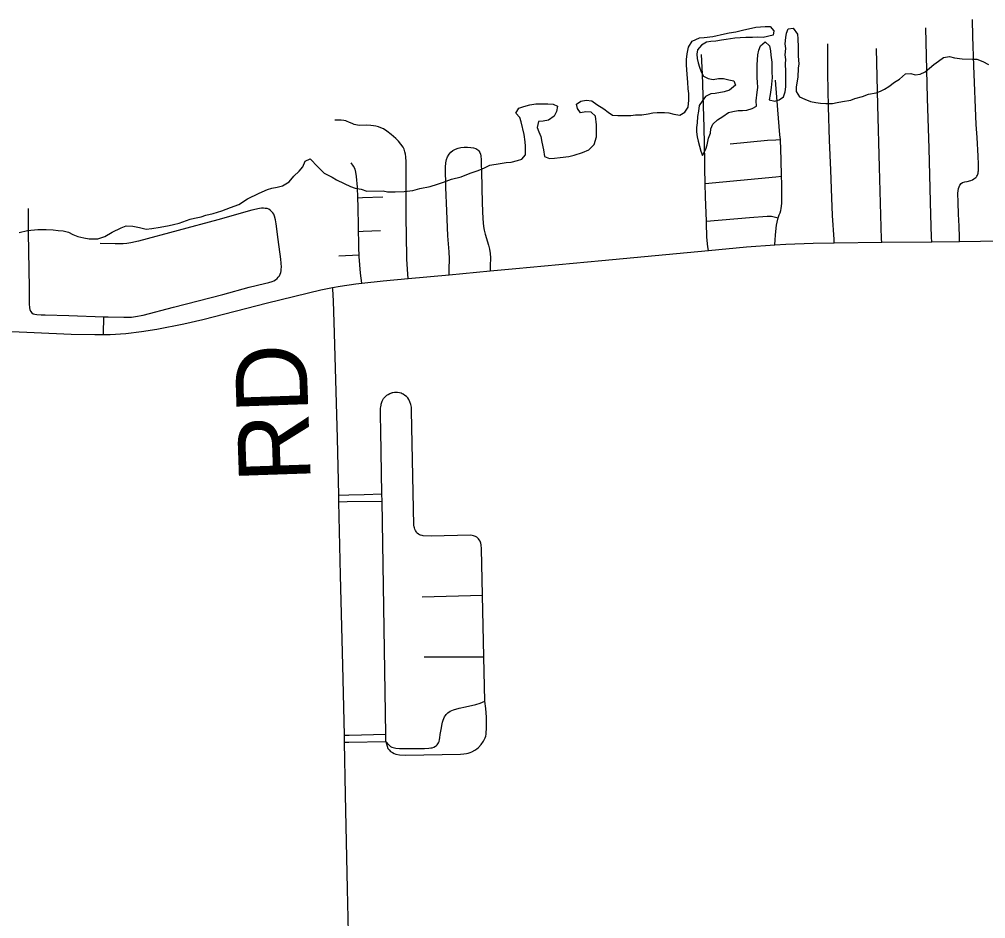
# Model space of a CAD drawing. Extents: x -12 to 34, y 0 to 22.
# Drawn here: x 3.492 to 4.257, y 17.22 to 17.932 of the extents above; entities that cross this region are included whole.
import ezdxf

# ---------------------------------------------------------------- set-up
doc = ezdxf.new("R2010")
doc.units = 0
for name, color, linetype in [('GM_X_Airport_Location_Class_3', 7, 'Continuous'), ('GM_X_County_Road', 7, 'Continuous'), ('GM_X_Major_Lake', 7, 'Continuous'), ('GM_X_Major_River', 7, 'Continuous'), ('GM_X_Minor_Lake', 7, 'Continuous'), ('GM_X_Township', 7, 'Continuous')]:
    doc.layers.add(name, color=color, linetype=linetype)

msp = doc.modelspace()

# ---------------------------------------------------------------- linework, layer by layer
at = {"layer": 'GM_X_Airport_Location_Class_3'}
msp.add_line((3.75011, 17.31777), (3.74933, 17.35937), dxfattribs=at)
for points in [[(3.74486, 17.54981), (3.74473, 17.55506), (3.74366, 17.60023), (3.74151, 17.68333), (3.74072, 17.7089), (3.74006, 17.71833), (3.73991, 17.71962)], [(3.74933, 17.35937), (3.74929, 17.36123), (3.74921, 17.3649), (3.74796, 17.42021), (3.74625, 17.49159), (3.74486, 17.54981)], [(3.75824, 16.94133), (3.75755, 16.97035), (3.75572, 17.05725), (3.75387, 17.15023), (3.75274, 17.19673), (3.75166, 17.24328), (3.75011, 17.31777)]]:
    msp.add_lwpolyline(points, dxfattribs=at)
at = {"layer": 'GM_X_Major_Lake'}
msp.add_lwpolyline([(3.47989, 17.68498), (3.5327, 17.68269), (3.55133, 17.68225), (3.55821, 17.68234), (3.56373, 17.68242), (3.57609, 17.68321), (3.5884, 17.68461), (3.60066, 17.68651), (3.62198, 17.69074), (3.63713, 17.69417), (3.68831, 17.70743), (3.73061, 17.71765), (3.73991, 17.71962), (3.74591, 17.72066), (3.75825, 17.7225), (3.76301, 17.72301), (3.77993, 17.72481), (3.79965, 17.72665), (3.8323, 17.72971), (3.86468, 17.73274), (3.88522, 17.73466), (3.95336, 17.74086), (4.03765, 17.74884), (4.06794, 17.75171), (4.09024, 17.75328), (4.09899, 17.7539), (4.12078, 17.7547), (4.13745, 17.7549), (4.17506, 17.75534), (4.21469, 17.7558), (4.23681, 17.75606), (4.27009, 17.75644)], dxfattribs=at)
at = {"layer": 'GM_X_Major_River'}
for p, q in [((3.74491, 17.74475), (3.76095, 17.74546)), ((3.77909, 17.55039), (3.77899, 17.55604)), ((3.7821, 17.36564), (3.77909, 17.55039)), ((3.81087, 17.47445), (3.85869, 17.47573)), ((3.85967, 17.42691), (3.85869, 17.47573)), ((3.81247, 17.4269), (3.85967, 17.42691)), ((3.86054, 17.39192), (3.85967, 17.42691)), ((3.7822, 17.35994), (3.7821, 17.36564))]:
    msp.add_line(p, q, dxfattribs=at)
for points in [[(4.23681, 17.75606), (4.23673, 17.75937), (4.23652, 17.76807), (4.2359, 17.77761), (4.23563, 17.78685), (4.23548, 17.79438), (4.23563, 17.79623), (4.23598, 17.79803), (4.23639, 17.79941), (4.23701, 17.80072), (4.23798, 17.80196), (4.23915, 17.80265), (4.24087, 17.80327), (4.2428, 17.80362), (4.24556, 17.80437), (4.24694, 17.80486), (4.24812, 17.80555), (4.24893, 17.80606), (4.24963, 17.80665), (4.25013, 17.80713), (4.25053, 17.80769), (4.25093, 17.80855), (4.25122, 17.80941), (4.25142, 17.81017), (4.25157, 17.81107), (4.25168, 17.81184), (4.2517, 17.81273), (4.2517, 17.81417), (4.2517, 17.81728), (4.25143, 17.8236), (4.25081, 17.83839), (4.24996, 17.84863), (4.24812, 17.89526), (4.24728, 17.91849), (4.24707, 17.93196)], [(4.21469, 17.7558), (4.21456, 17.75937), (4.21394, 17.77718), (4.21266, 17.82958), (4.21144, 17.86959), (4.20994, 17.92531)], [(4.13745, 17.7549), (4.13728, 17.75749), (4.13603, 17.77656), (4.13557, 17.79055), (4.13479, 17.8124), (4.13375, 17.83623), (4.13291, 17.86275), (4.13229, 17.88906), (4.13229, 17.91247)], [(4.17506, 17.75534), (4.17499, 17.75791), (4.17332, 17.81489), (4.17207, 17.86399), (4.17104, 17.90896)], [(4.03502, 17.80203), (4.03499, 17.81378), (4.03497, 17.81938), (4.03427, 17.84645), (4.03297, 17.88856), (4.03232, 17.9041)], [(4.09478, 17.83687), (4.09438, 17.84036), (4.09278, 17.86028), (4.09084, 17.88381)], [(3.79965, 17.72665), (3.79946, 17.73023), (3.79881, 17.74193), (3.79874, 17.74423), (3.79821, 17.77557), (3.7981, 17.80647), (3.79816, 17.8192), (3.79792, 17.82293), (3.79768, 17.82523), (3.79721, 17.82701), (3.79655, 17.82909), (3.79573, 17.83062), (3.79401, 17.83317), (3.79206, 17.83548), (3.78992, 17.83767), (3.78625, 17.84075), (3.78288, 17.84341), (3.78014, 17.84515), (3.7782, 17.84613), (3.77613, 17.8469), (3.77424, 17.84737), (3.7724, 17.84767), (3.77021, 17.84797), (3.76672, 17.84808), (3.76089, 17.84793), (3.75962, 17.84806), (3.75829, 17.84836), (3.75696, 17.84873), (3.75582, 17.84914), (3.75283, 17.85059), (3.75144, 17.85113), (3.75026, 17.85152), (3.74877, 17.85183), (3.74663, 17.85196), (3.74171, 17.85206)], [(4.05493, 17.83343), (4.08444, 17.83622), (4.09107, 17.83664), (4.09478, 17.83687)], [(4.09571, 17.80774), (4.0953, 17.82077), (4.09478, 17.83687)], [(3.8323, 17.72971), (3.83239, 17.73395), (3.83257, 17.74228), (3.83239, 17.7479), (3.83115, 17.76034), (3.83044, 17.78017), (3.82955, 17.79877), (3.82937, 17.81488), (3.82962, 17.81827), (3.83023, 17.82106), (3.83099, 17.82318), (3.83215, 17.82505), (3.83351, 17.82662), (3.83518, 17.82799), (3.83734, 17.82923), (3.83932, 17.82996), (3.84149, 17.83044), (3.84404, 17.83068), (3.84677, 17.83073), (3.84944, 17.83056), (3.85167, 17.83015), (3.85334, 17.82955), (3.8549, 17.8286), (3.85586, 17.82768), (3.85657, 17.82647), (3.85708, 17.82515), (3.85728, 17.82374), (3.85753, 17.8206), (3.85764, 17.81732), (3.85778, 17.8113), (3.85845, 17.78639), (3.8589, 17.77403), (3.85951, 17.76789), (3.85998, 17.76485), (3.86067, 17.76185), (3.86353, 17.75301), (3.86426, 17.75), (3.8647, 17.74654), (3.86497, 17.74299), (3.86479, 17.73679), (3.86468, 17.73274)], [(3.75987, 17.79066), (3.7596, 17.79894), (3.75889, 17.80744), (3.75836, 17.8108), (3.75765, 17.81328), (3.75637, 17.81576), (3.75448, 17.81818)], [(4.03502, 17.80203), (4.09105, 17.80731), (4.09571, 17.80774)], [(4.093, 17.77478), (4.09389, 17.77706), (4.09456, 17.77865), (4.09514, 17.78063), (4.09543, 17.78213), (4.09568, 17.78386), (4.09577, 17.78628), (4.09582, 17.79038), (4.09589, 17.8018), (4.09571, 17.80774)], [(4.03611, 17.77199), (4.03536, 17.7914), (4.03502, 17.80203)], [(3.75987, 17.79066), (3.76368, 17.79079), (3.77962, 17.79133)], [(3.76043, 17.7639), (3.76032, 17.7676), (3.76011, 17.78338), (3.75987, 17.79066)], [(3.55858, 17.69642), (3.56198, 17.69629), (3.57439, 17.69593), (3.58057, 17.69613), (3.58364, 17.69645), (3.58969, 17.6977), (3.61371, 17.70402), (3.65279, 17.71407), (3.67376, 17.71972), (3.68584, 17.72277), (3.6893, 17.72361), (3.692, 17.72432), (3.69342, 17.72492), (3.69475, 17.72575), (3.69589, 17.72668), (3.69676, 17.72765), (3.69769, 17.72878), (3.69833, 17.72998), (3.69881, 17.7314), (3.69906, 17.73272), (3.69922, 17.73395), (3.69929, 17.73564), (3.69881, 17.74187), (3.69663, 17.75746), (3.69526, 17.76995), (3.69473, 17.77316), (3.69397, 17.77613), (3.69331, 17.77762), (3.69253, 17.77877), (3.69159, 17.77983), (3.69049, 17.78068), (3.68923, 17.78155), (3.688, 17.78202), (3.6864, 17.78223), (3.68507, 17.78228), (3.68359, 17.78228), (3.68208, 17.7821), (3.67589, 17.78068), (3.64889, 17.77326), (3.58598, 17.75619), (3.57994, 17.75483), (3.57689, 17.75434), (3.57382, 17.75406), (3.56762, 17.75408), (3.5557, 17.75434)], [(3.49869, 17.78201), (3.49858, 17.77529), (3.49861, 17.76288), (3.4993, 17.71941), (3.49938, 17.70987), (3.49951, 17.70667), (3.49962, 17.70351), (3.4999, 17.7021), (3.50051, 17.70085), (3.50147, 17.69961), (3.50256, 17.69876), (3.50389, 17.69836), (3.50554, 17.69823), (3.50892, 17.698), (3.51208, 17.69788), (3.53096, 17.69746), (3.55858, 17.69642)], [(4.03611, 17.77199), (4.07018, 17.77501), (4.0843, 17.77614), (4.08766, 17.77614), (4.093, 17.77478)], [(4.09024, 17.75328), (4.09063, 17.7573), (4.0908, 17.76113), (4.09136, 17.76665), (4.09175, 17.76904), (4.09217, 17.77135), (4.093, 17.77478)], [(4.03765, 17.74884), (4.0373, 17.75189), (4.03644, 17.75945), (4.03616, 17.7707), (4.03611, 17.77199)], [(3.76043, 17.7639), (3.76421, 17.76405), (3.77785, 17.76459)], [(3.76095, 17.74546), (3.76067, 17.75041), (3.76067, 17.75591), (3.76043, 17.7639)], [(3.76301, 17.72301), (3.76194, 17.7308), (3.7614, 17.73753), (3.76102, 17.74404), (3.76095, 17.74546)], [(3.55821, 17.68234), (3.55828, 17.68513), (3.55852, 17.69405), (3.55858, 17.69642)], [(3.77899, 17.55604), (3.77818, 17.60598), (3.77789, 17.6182), (3.77794, 17.62291), (3.77796, 17.62407), (3.77803, 17.62499), (3.77826, 17.6264), (3.7784, 17.62717), (3.77863, 17.62805), (3.77913, 17.62961), (3.77962, 17.63056), (3.78027, 17.6315), (3.78089, 17.63232), (3.78149, 17.63289), (3.7822, 17.63357), (3.78292, 17.63414), (3.78392, 17.6348), (3.78536, 17.63553), (3.78676, 17.63606)], [(3.85869, 17.47573), (3.85797, 17.51255), (3.8577, 17.51568), (3.85736, 17.51713), (3.85678, 17.51864), (3.85613, 17.51971), (3.85553, 17.52044), (3.85494, 17.52109), (3.8541, 17.52173), (3.85318, 17.52228), (3.85235, 17.52268), (3.85148, 17.52292), (3.85047, 17.52315), (3.84909, 17.52324), (3.81807, 17.52265), (3.81178, 17.52278), (3.8109, 17.52299), (3.80944, 17.52346), (3.80885, 17.52371), (3.80803, 17.52421), (3.80701, 17.52506), (3.80647, 17.52556), (3.80598, 17.52632), (3.80553, 17.52699), (3.80499, 17.52819), (3.80472, 17.52905), (3.80449, 17.53008), (3.80432, 17.53124), (3.80251, 17.62177), (3.80228, 17.62488), (3.80187, 17.62677), (3.80117, 17.629), (3.80031, 17.63075), (3.79938, 17.63202), (3.79833, 17.63313), (3.79718, 17.63409), (3.7958, 17.63494), (3.79492, 17.63539), (3.7941, 17.63572), (3.79289, 17.63606), (3.79137, 17.6363), (3.79002, 17.63639), (3.78906, 17.63631), (3.78767, 17.6362), (3.78676, 17.63606)], [(3.74473, 17.55506), (3.75279, 17.55523), (3.76487, 17.5555), (3.77899, 17.55604)], [(3.74486, 17.54981), (3.75144, 17.54992), (3.77909, 17.55039)], [(3.7822, 17.35994), (3.78372, 17.35451), (3.78464, 17.35326), (3.78578, 17.35204), (3.78725, 17.35114), (3.78855, 17.35041), (3.79002, 17.34992), (3.79279, 17.34935), (3.79759, 17.34898), (3.84123, 17.34995), (3.84385, 17.35009), (3.84589, 17.35042), (3.84739, 17.35076), (3.84891, 17.35123), (3.85029, 17.35181), (3.85249, 17.35294), (3.85412, 17.35409), (3.85544, 17.35526), (3.85758, 17.35752), (3.85937, 17.36008), (3.86072, 17.36287), (3.8612, 17.36426), (3.86153, 17.36585), (3.86169, 17.36761), (3.86177, 17.36956), (3.86185, 17.37206), (3.8618, 17.3792), (3.86131, 17.38615), (3.86054, 17.39192)], [(3.7822, 17.35994), (3.78472, 17.35693), (3.78578, 17.35603), (3.78692, 17.35538), (3.78782, 17.35506), (3.7901, 17.35465), (3.79287, 17.3544), (3.79515, 17.35429), (3.80142, 17.35434), (3.81265, 17.35451), (3.8162, 17.35466), (3.8176, 17.3548), (3.81887, 17.35504), (3.8202, 17.35536), (3.82155, 17.35623), (3.82224, 17.35684), (3.82288, 17.35738), (3.82382, 17.35888), (3.82422, 17.36003), (3.82456, 17.36141), (3.8248, 17.3628), (3.82512, 17.36548), (3.82582, 17.36949), (3.82659, 17.37387), (3.82691, 17.37534), (3.8274, 17.37688), (3.82793, 17.37828), (3.82864, 17.37951), (3.82927, 17.38055), (3.83, 17.38136), (3.83066, 17.38202), (3.83131, 17.38257), (3.83294, 17.38384), (3.83575, 17.38509), (3.84011, 17.38625), (3.84532, 17.3874), (3.85344, 17.38931), (3.85675, 17.39037), (3.86054, 17.39192)], [(3.74921, 17.3649), (3.75311, 17.36498), (3.7821, 17.36564)], [(3.74933, 17.35937), (3.7528, 17.35944), (3.7822, 17.35994)]]:
    msp.add_lwpolyline(points, dxfattribs=at)
at = {"layer": 'GM_X_Minor_Lake'}
for points in [[(3.85536, 17.81232), (3.86029, 17.81424), (3.86445, 17.81654), (3.8728, 17.81772), (3.87735, 17.8185), (3.88152, 17.8189), (3.88645, 17.82006), (3.88987, 17.82122), (3.89288, 17.82465), (3.89285, 17.8315), (3.89245, 17.83492), (3.89166, 17.84061), (3.88934, 17.85086), (3.88818, 17.85428), (3.88512, 17.85769), (3.88738, 17.8615), (3.89155, 17.86304), (3.8961, 17.8642), (3.90103, 17.86499), (3.91052, 17.86503), (3.9147, 17.86467), (3.91813, 17.86316), (3.91739, 17.85898), (3.91551, 17.85517), (3.91097, 17.85211), (3.9068, 17.85133), (3.903, 17.85093), (3.90189, 17.84636), (3.90342, 17.84295), (3.90496, 17.83915), (3.90574, 17.8346), (3.90691, 17.82852), (3.9077, 17.8232), (3.91188, 17.8217), (3.91568, 17.8221), (3.92023, 17.8225), (3.92706, 17.82329), (3.93123, 17.82445), (3.93805, 17.82638), (3.94298, 17.82869), (3.94713, 17.83289), (3.949, 17.83898), (3.94895, 17.84848), (3.94816, 17.85532), (3.94473, 17.85835), (3.94055, 17.85871), (3.93638, 17.85793), (3.93408, 17.86134), (3.9333, 17.86476), (3.93671, 17.86705), (3.94088, 17.86783), (3.94544, 17.86747), (3.94925, 17.86445), (3.95496, 17.86105), (3.95839, 17.85841), (3.96182, 17.85615), (3.966, 17.85579), (3.97625, 17.85583), (3.98005, 17.85623), (3.98498, 17.85625), (3.98991, 17.85704), (3.99371, 17.85781), (3.99712, 17.85821), (4.00282, 17.85824), (4.00623, 17.85787), (4.01041, 17.85675), (4.01498, 17.85601), (4.01914, 17.85831), (4.02178, 17.86251), (4.02213, 17.86783), (4.0221, 17.87315), (4.0217, 17.87695), (4.0213, 17.88227), (4.02089, 17.88835), (4.02047, 17.89595), (4.02045, 17.90013), (4.0208, 17.90469), (4.02191, 17.91002), (4.02493, 17.9146), (4.03061, 17.91728), (4.03441, 17.91768), (4.04123, 17.91847), (4.05034, 17.92042), (4.05413, 17.92119), (4.05944, 17.92198), (4.06589, 17.92353), (4.07195, 17.92508), (4.07537, 17.92586), (4.08258, 17.92627), (4.08676, 17.92629), (4.08943, 17.92288), (4.08907, 17.91946), (4.0811, 17.91752), (4.07693, 17.91788), (4.07275, 17.91748), (4.06744, 17.91746), (4.06288, 17.91743), (4.05871, 17.91703), (4.05529, 17.91664), (4.05188, 17.91586), (4.04808, 17.91547)], [(4.04808, 17.91547), (4.04353, 17.91468), (4.03974, 17.91429), (4.03632, 17.91389), (4.03216, 17.91159), (4.02914, 17.90777), (4.0284, 17.90435), (4.0288, 17.90093), (4.02957, 17.89751), (4.03073, 17.8941), (4.03189, 17.8903), (4.0338, 17.88689), (4.03761, 17.88501), (4.04141, 17.88426), (4.04558, 17.88504), (4.04976, 17.88506), (4.05394, 17.88394), (4.05774, 17.8832), (4.05927, 17.87978), (4.05436, 17.87596), (4.05019, 17.87442), (4.04298, 17.87325), (4.03957, 17.87285), (4.0354, 17.87093), (4.03276, 17.86712), (4.0305, 17.86368), (4.02977, 17.85912), (4.02903, 17.85494), (4.02867, 17.84999), (4.02831, 17.84619), (4.02833, 17.84277), (4.02873, 17.83897), (4.02951, 17.83555), (4.03067, 17.83138), (4.03183, 17.82758), (4.03298, 17.82417), (4.03561, 17.82912), (4.03673, 17.83254), (4.03785, 17.83787), (4.03935, 17.84168), (4.03971, 17.8451), (4.04121, 17.84891), (4.04499, 17.85235), (4.04915, 17.85503), (4.05369, 17.85809), (4.0571, 17.85887), (4.06128, 17.85965), (4.06469, 17.85966), (4.06811, 17.86006), (4.07228, 17.86122), (4.07569, 17.86314), (4.07566, 17.86732), (4.07639, 17.87416), (4.07675, 17.87797), (4.07673, 17.88215), (4.07633, 17.88557), (4.07628, 17.89583), (4.07664, 17.90001), (4.077, 17.90381), (4.07774, 17.90762), (4.07886, 17.91104), (4.08264, 17.9141), (4.08607, 17.91108), (4.08685, 17.9069), (4.08725, 17.90348), (4.08804, 17.89816), (4.08808, 17.89018), (4.0881, 17.886), (4.08738, 17.87801), (4.08665, 17.87231), (4.08591, 17.86812), (4.09047, 17.86701), (4.09388, 17.86816), (4.09729, 17.87046), (4.09841, 17.87465), (4.09915, 17.87845), (4.09909, 17.89061), (4.09867, 17.89669), (4.09904, 17.90011), (4.09864, 17.90392), (4.09899, 17.90886), (4.09859, 17.91266), (4.09895, 17.9176), (4.09969, 17.92102), (4.10081, 17.92445), (4.10499, 17.92485), (4.10843, 17.92031), (4.10845, 17.9165), (4.10886, 17.91004), (4.10889, 17.90282), (4.1093, 17.89674), (4.10894, 17.89332), (4.1086, 17.8861), (4.10712, 17.87849), (4.10714, 17.87468), (4.10982, 17.87052), (4.114, 17.86863), (4.11857, 17.86676), (4.12275, 17.86601), (4.12655, 17.86565), (4.13073, 17.86529)], [(4.13073, 17.86529), (4.13604, 17.86532), (4.13983, 17.86609), (4.14401, 17.86687), (4.15045, 17.86804), (4.15387, 17.8692), (4.15993, 17.87075), (4.16448, 17.87267), (4.17055, 17.87384), (4.17396, 17.875), (4.17737, 17.87653), (4.18077, 17.87883), (4.18531, 17.88227), (4.1891, 17.88457), (4.19401, 17.88877), (4.19819, 17.88917), (4.20161, 17.88804), (4.2054, 17.88844), (4.20957, 17.89036), (4.21637, 17.8961), (4.22016, 17.89878), (4.22394, 17.90183), (4.22887, 17.90262), (4.23267, 17.90149), (4.23875, 17.90076), (4.2471, 17.90042), (4.25052, 17.90044), (4.25509, 17.89856), (4.25966, 17.8963)], [(3.49152, 17.7631), (3.49797, 17.76465), (3.50632, 17.76545), (3.51277, 17.76548), (3.51847, 17.76512), (3.52227, 17.76476), (3.52644, 17.7644), (3.53062, 17.76328), (3.53405, 17.7614), (3.53786, 17.75989), (3.5428, 17.75878), (3.54698, 17.75804), (3.55381, 17.75807), (3.55949, 17.76), (3.56517, 17.76344), (3.57237, 17.7669), (3.57616, 17.76844), (3.58148, 17.76808), (3.58679, 17.76697), (3.59212, 17.76585), (3.59667, 17.76625), (3.60312, 17.76742), (3.61033, 17.7686), (3.61374, 17.76937), (3.61829, 17.77053), (3.62701, 17.77362), (3.63042, 17.77439), (3.63573, 17.77556), (3.63952, 17.77672), (3.6452, 17.77826), (3.65203, 17.78019), (3.65885, 17.78289), (3.66567, 17.7852), (3.67248, 17.78979), (3.68157, 17.7944), (3.68839, 17.79709), (3.6918, 17.79825), (3.69597, 17.79903), (3.70014, 17.80019), (3.70544, 17.80325), (3.70922, 17.80783), (3.71337, 17.81165), (3.71639, 17.81509), (3.71827, 17.81966), (3.72205, 17.82158), (3.72816, 17.81514), (3.73312, 17.81022), (3.73959, 17.80683), (3.74302, 17.80495), (3.74911, 17.80194), (3.75406, 17.79968), (3.75786, 17.79818), (3.76242, 17.79744), (3.76698, 17.79594), (3.77989, 17.796), (3.78331, 17.79525), (3.78939, 17.79528), (3.7966, 17.7957), (3.80343, 17.79649), (3.80912, 17.79804), (3.81708, 17.79959), (3.82314, 17.80152), (3.82769, 17.80306), (3.83413, 17.80537), (3.84172, 17.80731), (3.84892, 17.81001), (3.85536, 17.81232)]]:
    msp.add_lwpolyline(points, dxfattribs=at)
at = {"layer": 'GM_X_Township'}
msp.add_lwpolyline([(3.47989, 17.68498), (3.5327, 17.68269), (3.55133, 17.68225), (3.55821, 17.68234), (3.56373, 17.68242), (3.57609, 17.68321), (3.5884, 17.68461), (3.60066, 17.68651), (3.62198, 17.69074), (3.63713, 17.69417), (3.68831, 17.70743), (3.73061, 17.71765), (3.73991, 17.71962), (3.74591, 17.72066), (3.75825, 17.7225), (3.76301, 17.72301), (3.77993, 17.72481), (3.79965, 17.72665), (3.8323, 17.72971), (3.86468, 17.73274), (3.88522, 17.73466), (3.95336, 17.74086), (4.03765, 17.74884), (4.06794, 17.75171), (4.09024, 17.75328), (4.09899, 17.7539), (4.12078, 17.7547), (4.13745, 17.7549), (4.17506, 17.75534), (4.21469, 17.7558), (4.23681, 17.75606), (4.27009, 17.75644)], dxfattribs=at)

# ---------------------------------------------------------------- texts
at = {"layer": 'GM_X_County_Road'}
msp.add_text('RD', height=0.056818, rotation=91.97716, dxfattribs=at).set_placement((3.72261, 17.56609))

doc.saveas('drawing.dxf')
